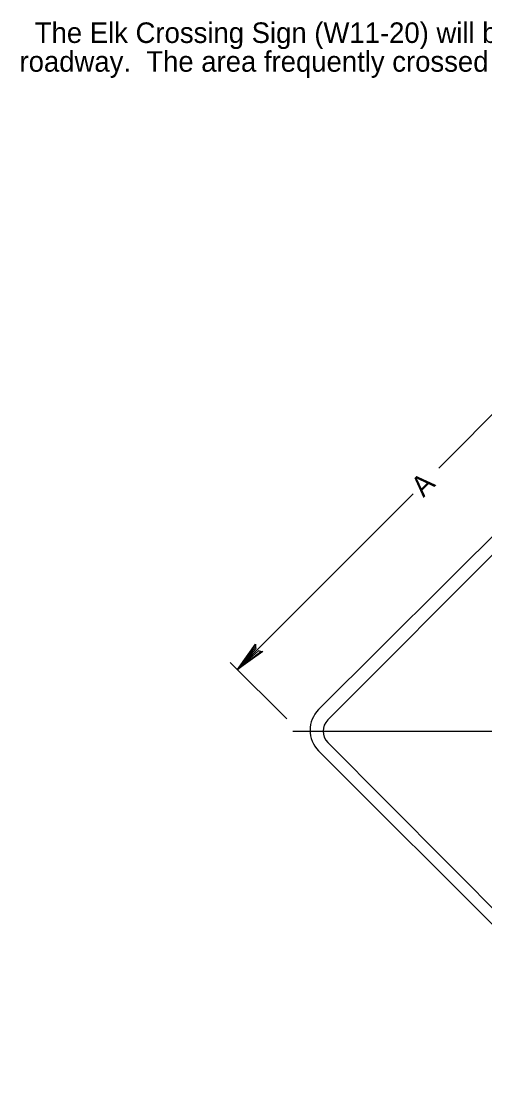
# Model space of a CAD drawing. Extents: x 0.013 to 0.184, y 0.005 to 0.259.
# Drawn here: x 0.0293 to 0.0857, y 0.1074 to 0.2371 of the extents above; entities that cross this region are included whole.
import ezdxf

# ---------------------------------------------------------------- set-up
doc = ezdxf.new("R2010")
doc.units = 0
for name, color, linetype in [('11', 7, 'Continuous'), ('2', 7, 'Continuous'), ('3', 7, 'Continuous')]:
    doc.layers.add(name, color=color, linetype=linetype)

# ---------------------------------------------------------------- blocks, each defined once
blk = doc.blocks.new('RARROW')
at = {"layer": '3'}
for p, q in [((-2.156, 0.28500000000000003), (-2.2665, 0.384625)), ((-2.2665, 0.384625), (0, 0)), ((0, 0), (-2.2665, -0.379125)), ((-2.156, 0.28500000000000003), (-2.075625, 0.12075)), ((0, 0), (-2.156, 0.28500000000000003)), ((-2.14975, -0.2705), (0, 0)), ((-2.075625, 0.12075), (0, 0)), ((0, 0), (-2.074, -0.108)), ((-2.2665, -0.379125), (-2.14975, -0.2705)), ((-2.074, -0.108), (-2.14975, -0.2705))]:
    blk.add_line(p, q, dxfattribs=at)

msp = doc.modelspace()

# ---------------------------------------------------------------- linework, layer by layer
at = {"layer": '11'}
for p, q in [((0.0655, 0.153375), (0.1065, 0.19425)), ((0.1065, 0.107375), (0.0655, 0.148375))]:
    msp.add_line(p, q, dxfattribs=at)
msp.add_arc((0.06803372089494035, 0.15087500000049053), 0.0035594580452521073, 135.38381666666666, 224.61618055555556, dxfattribs=at)
at = {"layer": '3'}
for p, q in [((0.080125, 0.18275), (0.1015, 0.20425000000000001)), ((0.066625, 0.152125), (0.1075, 0.193125)), ((0.077, 0.179625), (0.055625, 0.15825)), ((0.061625, 0.15225), (0.05475, 0.15912500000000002)), ((0.062375, 0.15075), (0.1545, 0.15075)), ((0.1075, 0.10825), (0.066625, 0.149375))]:
    msp.add_line(p, q, dxfattribs=at)
msp.add_arc((0.06801854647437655, 0.1507499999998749), 0.0019577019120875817, 135.38381944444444, 224.61618333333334, dxfattribs=at)

# ---------------------------------------------------------------- block references
at = {"layer": '3', "xscale": 0.0016545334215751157, "yscale": 0.001636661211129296, "rotation": -135}
msp.add_blockref('RARROW', (0.055625, 0.15825), dxfattribs=at)

# ---------------------------------------------------------------- texts
at = {"layer": '2'}
for s, p in [('  The Elk Crossing Sign (W11-20) will be authorized to warn of the unexpected hazard of elk crossing the', (0.029125, 0.23450000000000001)), ('roadway.  The area frequently crossed by elk will be designated by the Game Commission.', (0.029125, 0.23100025))]:
    msp.add_text(s, height=0.0024997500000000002, dxfattribs=at).set_placement(p)
at = {"layer": '3'}
msp.add_text('A', height=0.0024997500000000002, rotation=45, dxfattribs=at).set_placement((0.07825, 0.179125))

doc.saveas('drawing.dxf')
